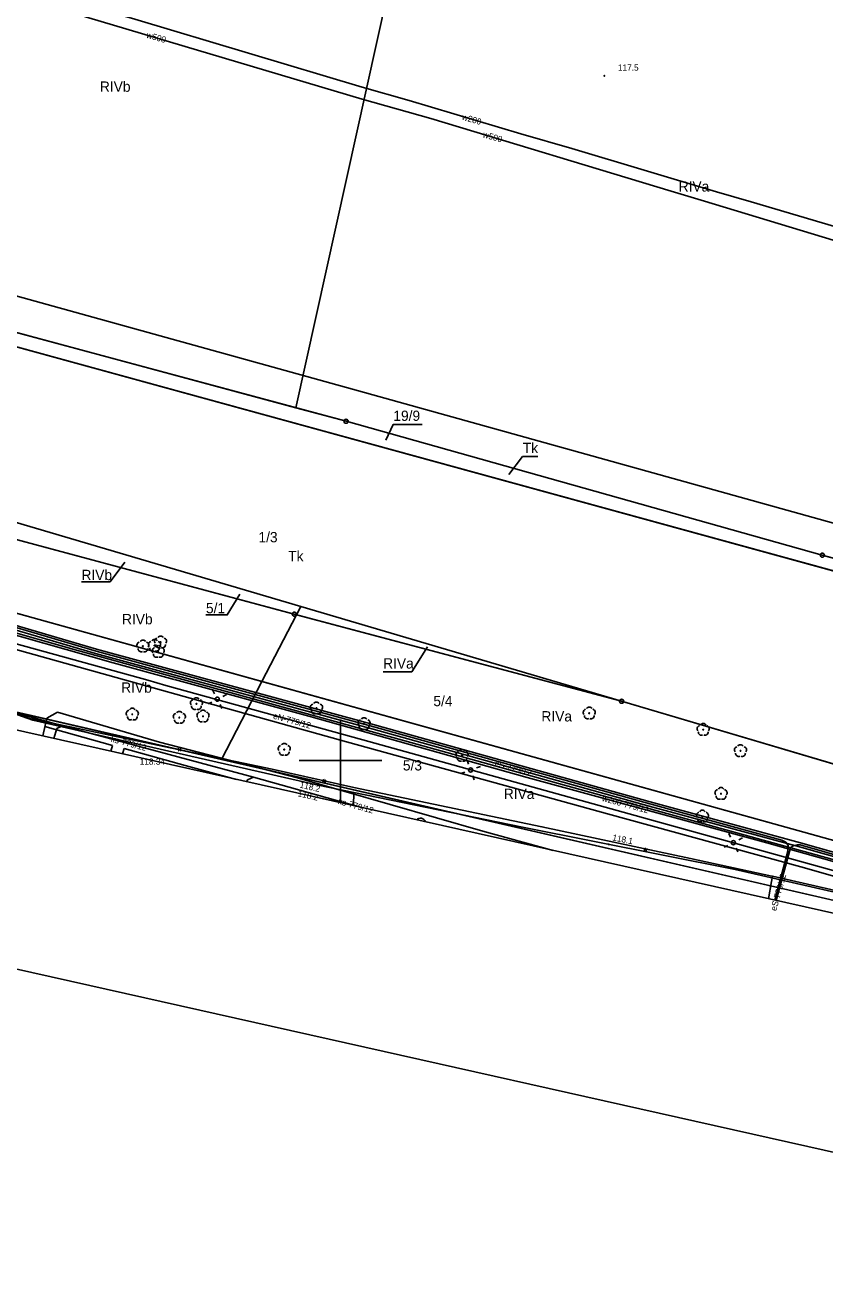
# Model space of a CAD drawing. Extents: x 6424617 to 6425697, y 5665845 to 5667190.
# Drawn here: x 6424861.7 to 6424958.8, y 5665936 to 5666089.2 of the extents above; entities that cross this region are included whole.
import ezdxf

# ---------------------------------------------------------------- set-up
doc = ezdxf.new("R2010")
doc.units = 0
for name, color, linetype in [('Warstwa 1', 7, 'Continuous'), ('Warstwa 10', 7, 'Continuous'), ('Warstwa 11', 7, 'Continuous'), ('Warstwa 12', 7, 'Continuous'), ('Warstwa 13', 7, 'Continuous'), ('Warstwa 15', 7, 'Continuous'), ('Warstwa 2', 7, 'Continuous'), ('Warstwa 6', 7, 'Continuous'), ('Warstwa 62', 7, 'Continuous'), ('Warstwa 63', 7, 'Continuous'), ('Warstwa 8', 7, 'Continuous')]:
    doc.layers.add(name, color=color, linetype=linetype)

msp = doc.modelspace()

# ---------------------------------------------------------------- linework, layer by layer
at = {"layer": 'Warstwa 1'}
for p, q in [((6424894.58, 5666042.82), (6424908.97, 5666107.79)), ((6424894.58, 5666042.82), (6424908.97, 5666107.79)), ((6424836.07, 5666058.54), (6424894.58, 5666042.82)), ((6424836.07, 5666058.54), (6424894.58, 5666042.82)), ((6424835.72, 5666057.05), (6424969.12, 5666020.47)), ((6424835.72, 5666057.05), (6424969.12, 5666020.47)), ((6424894.58, 5666042.82), (6424900.68, 5666041.18)), ((6424894.58, 5666042.82), (6424900.68, 5666041.18)), ((6424900.68, 5666041.18), (6424958.47, 5666024.93)), ((6424900.68, 5666041.18), (6424958.47, 5666024.93)), ((6424860.53, 5666028.94), (6424895.19, 5666018.7)), ((6424860.53, 5666028.94), (6424895.19, 5666018.7)), ((6424860.2, 5666026.96), (6424894.67, 5666017.7)), ((6424860.2, 5666026.96), (6424894.67, 5666017.7)), ((6424958.47, 5666024.93), (6424969.49, 5666021.95)), ((6424958.47, 5666024.93), (6424969.49, 5666021.95)), ((6424858.78, 5666018.4), (6424890.46, 5666009.6)), ((6424858.78, 5666018.4), (6424890.46, 5666009.6)), ((6424890.46, 5666009.6), (6424894.67, 5666017.7)), ((6424890.46, 5666009.6), (6424894.67, 5666017.7)), ((6424894.67, 5666017.7), (6424895.19, 5666018.7)), ((6424894.67, 5666017.7), (6424895.19, 5666018.7)), ((6424894.67, 5666017.7), (6424934.12, 5666007.2)), ((6424894.67, 5666017.7), (6424934.12, 5666007.2)), ((6424895.19, 5666018.7), (6424934.12, 5666007.2)), ((6424895.19, 5666018.7), (6424934.12, 5666007.2)), ((6424885.54, 5666000.14), (6424890.46, 5666009.6)), ((6424885.54, 5666000.14), (6424890.46, 5666009.6)), ((6424890.46, 5666009.6), (6424961.6, 5665989.83)), ((6424890.46, 5666009.6), (6424961.6, 5665989.83)), ((6424856.84, 5666006.75), (6424885.54, 5666000.14)), ((6424856.84, 5666006.75), (6424885.54, 5666000.14)), ((6424934.12, 5666007.2), (6424963.73, 5665998.45)), ((6424934.12, 5666007.2), (6424963.73, 5665998.45)), ((6424885.54, 5666000.14), (6424959.92, 5665983.01)), ((6424885.54, 5666000.14), (6424959.92, 5665983.01))]:
    msp.add_line(p, q, dxfattribs=at)
at = {"layer": 'Warstwa 10'}
for points in [[(6424857.53, 5666006.67), (6424862.3, 5666005.11), (6424867.94, 5666003.94), (6424882.04, 5666001), (6424891.71, 5665998.95), (6424901.61, 5665996.74)], [(6424952.41, 5665985.97), (6424952.35, 5665985.99), (6424942.46, 5665988.12), (6424924.44, 5665991.97), (6424901.61, 5665996.74)], [(6425060.44, 5665958.92), (6425057.61, 5665959.71), (6425030.82, 5665967.28), (6425026.23, 5665968.58), (6425020.29, 5665970.3), (6425010.94, 5665972.53), (6424974.55, 5665980.91), (6424952.41, 5665985.97)]]:
    msp.add_lwpolyline(points, dxfattribs=at)
for centre in [(6424900.68, 5666041.18), (6424958.47, 5666024.93), (6424894.39, 5666017.77), (6424934.12, 5666007.2)]:
    msp.add_circle(centre, 0.25, dxfattribs=at)
at = {"layer": 'Warstwa 11'}
for centre in [(6424878.16, 5666014.36), (6424876.02, 5666013.88), (6424877.43, 5666013.96), (6424877.88, 5666013.21), (6424882.51, 5666006.89), (6424874.73, 5666005.61), (6424880.44, 5666005.22), (6424883.31, 5666005.37), (6424897.08, 5666006.35), (6424930.19, 5666005.74), (6424902.86, 5666004.45), (6424944.02, 5666003.75), (6424893.17, 5666001.34), (6424914.75, 5666000.61), (6424948.54, 5666001.18), (6424946.18, 5665995.98), (6424943.92, 5665993.23)]:
    msp.add_circle(centre, 0.05, dxfattribs=at)
for centre, start, end in [((6424875.66, 5666014), 102.1471, 221.8529), ((6424876.02, 5666014.25), 30.1471, 149.8529), ((6424876.38, 5666014), 318.1471, 77.8529), ((6424877.07, 5666014.08), 102.1471, 221.8529), ((6424877.43, 5666014.33), 30.1471, 149.8529), ((6424877.8, 5666014.48), 102.1471, 221.8529), ((6424878.16, 5666014.74), 30.1471, 149.8529), ((6424877.79, 5666014.08), 318.1471, 77.8529), ((6424878.52, 5666014.48), 318.1471, 77.8529), ((6424875.8, 5666013.58), 174.1471, 293.8529), ((6424876.24, 5666013.58), 246.1471, 5.8529), ((6424877.21, 5666013.66), 174.1471, 293.8529), ((6424877.52, 5666013.33), 102.1471, 221.8529), ((6424877.66, 5666012.91), 174.1471, 293.8529), ((6424877.65, 5666013.66), 246.1471, 5.8529), ((6424877.94, 5666014.06), 174.1471, 293.8529), ((6424877.88, 5666013.58), 30.1471, 149.8529), ((6424878.1, 5666012.91), 246.1471, 5.8529), ((6424878.38, 5666014.06), 246.1471, 5.8529), ((6424878.24, 5666013.33), 318.1471, 77.8529), ((6424882.15, 5666007.01), 102.1471, 221.8529), ((6424882.29, 5666006.59), 174.1471, 293.8529), ((6424882.51, 5666007.26), 30.1471, 149.8529), ((6424882.73, 5666006.59), 246.1471, 5.8529), ((6424882.87, 5666007.01), 318.1471, 77.8529), ((6424896.72, 5666006.47), 102.1471, 221.8529), ((6424897.08, 5666006.73), 30.1471, 149.8529), ((6424897.44, 5666006.47), 318.1471, 77.8529), ((6424874.37, 5666005.73), 102.1471, 221.8529), ((6424874.51, 5666005.31), 174.1471, 293.8529), ((6424874.73, 5666005.99), 30.1471, 149.8529), ((6424874.95, 5666005.31), 246.1471, 5.8529), ((6424875.09, 5666005.73), 318.1471, 77.8529), ((6424880.08, 5666005.34), 102.1471, 221.8529), ((6424880.44, 5666005.59), 30.1471, 149.8529), ((6424880.8, 5666005.34), 318.1471, 77.8529), ((6424882.95, 5666005.49), 102.1471, 221.8529), ((6424883.09, 5666005.07), 174.1471, 293.8529), ((6424883.31, 5666005.75), 30.1471, 149.8529), ((6424883.53, 5666005.07), 246.1471, 5.8529), ((6424883.67, 5666005.49), 318.1471, 77.8529), ((6424896.86, 5666006.05), 174.1471, 293.8529), ((6424897.3, 5666006.05), 246.1471, 5.8529), ((6424902.86, 5666004.83), 30.1471, 149.8529), ((6424929.83, 5666005.86), 102.1471, 221.8529), ((6424929.97, 5666005.44), 174.1471, 293.8529), ((6424930.19, 5666006.12), 30.1471, 149.8529), ((6424930.41, 5666005.44), 246.1471, 5.8529), ((6424930.55, 5666005.86), 318.1471, 77.8529), ((6424880.22, 5666004.92), 174.1471, 293.8529), ((6424880.66, 5666004.92), 246.1471, 5.8529), ((6424902.5, 5666004.57), 102.1471, 221.8529), ((6424902.64, 5666004.15), 174.1471, 293.8529), ((6424903.08, 5666004.15), 246.1471, 5.8529), ((6424903.22, 5666004.57), 318.1471, 77.8529), ((6424943.66, 5666003.87), 102.1471, 221.8529), ((6424944.02, 5666004.12), 30.1471, 149.8529), ((6424944.38, 5666003.87), 318.1471, 77.8529), ((6424893.17, 5666001.71), 30.1471, 149.8529), ((6424943.8, 5666003.45), 174.1471, 293.8529), ((6424944.24, 5666003.45), 246.1471, 5.8529), ((6424892.81, 5666001.46), 102.1471, 221.8529), ((6424892.95, 5666001.04), 174.1471, 293.8529), ((6424893.39, 5666001.04), 246.1471, 5.8529), ((6424893.53, 5666001.46), 318.1471, 77.8529), ((6424914.39, 5666000.73), 102.1471, 221.8529), ((6424914.75, 5666000.99), 30.1471, 149.8529), ((6424915.11, 5666000.73), 318.1471, 77.8529), ((6424948.18, 5666001.3), 102.1471, 221.8529), ((6424948.32, 5666000.88), 174.1471, 293.8529), ((6424948.54, 5666001.55), 30.1471, 149.8529), ((6424948.76, 5666000.88), 246.1471, 5.8529), ((6424948.9, 5666001.3), 318.1471, 77.8529), ((6424914.53, 5666000.31), 174.1471, 293.8529), ((6424914.97, 5666000.31), 246.1471, 5.8529), ((6424945.82, 5665996.1), 102.1471, 221.8529), ((6424946.18, 5665996.36), 30.1471, 149.8529), ((6424946.54, 5665996.1), 318.1471, 77.8529), ((6424945.96, 5665995.68), 174.1471, 293.8529), ((6424946.4, 5665995.68), 246.1471, 5.8529), ((6424943.56, 5665993.35), 102.1471, 221.8529), ((6424943.7, 5665992.93), 174.1471, 293.8529), ((6424943.92, 5665993.61), 30.1471, 149.8529), ((6424944.14, 5665992.93), 246.1471, 5.8529), ((6424944.28, 5665993.35), 318.1471, 77.8529)]:
    msp.add_arc(centre, 0.375, start, end, dxfattribs=at)
at = {"layer": 'Warstwa 12'}
for points in [[(6424670.55, 5666139.91), (6424698.76, 5666131.82), (6424719.05, 5666126.08), (6424734.31, 5666121.24), (6424747.33, 5666117.09), (6424755.84, 5666114.39), (6424782.04, 5666115.46), (6424794.27, 5666116), (6424797.46, 5666115.3), (6424803.11, 5666113.21), (6424814.01, 5666109.23), (6424817.9, 5666107.86), (6424829.59, 5666103.93), (6424845.05, 5666099.1), (6424865.08, 5666092.88), (6424875.03, 5666089.96), (6424902.64, 5666081.73)], [(6424902.62, 5666080.27), (6424864.14, 5666091.7), (6424860.63, 5666092.76), (6424847.91, 5666096.78), (6424844.38, 5666097.93), (6424839.02, 5666099.64), (6424837.77, 5666100.03), (6424836.46, 5666100.46), (6424831.87, 5666102), (6424826.41, 5666103.77), (6424815.64, 5666107.27), (6424797.06, 5666114.5), (6424794.67, 5666114.9), (6424793, 5666114.76), (6424775.51, 5666113.22), (6424757.94, 5666111.72), (6424745.4, 5666115.53), (6424721.25, 5666122.92), (6424708.57, 5666126.76), (6424700.98, 5666128.93), (6424670.1, 5666137.9)], [(6424902.64, 5666081.73), (6424908.32, 5666080.09), (6424921.88, 5666076.04), (6424928.08, 5666074.29), (6424945.63, 5666069.01)], [(6424902.62, 5666080.27), (6424910.96, 5666077.91), (6424940.11, 5666069.08)], [(6424809.94, 5666070.66), (6424827.91, 5666065.56), (6424854, 5666058.2), (6424902.19, 5666044.87)], [(6424940.11, 5666069.08), (6424943.78, 5666067.99), (6424962.88, 5666062.22), (6424972.24, 5666059.43), (6424989.04, 5666054.69), (6425022.79, 5666045.28), (6425030.07, 5666043.18), (6425037.86, 5666041), (6425041.81, 5666039.94), (6425072.97, 5666031.24), (6425127.39, 5666016.19)], [(6425192.87, 5665999.59), (6425180.06, 5666003.17), (6425173.22, 5666005.07), (6425118.59, 5666020.43), (6425101.46, 5666025.04), (6425073.28, 5666032.33), (6425066.83, 5666034.26), (6425056.27, 5666037.28), (6425042.06, 5666041.29), (6425038.43, 5666042.25), (6425029.69, 5666044.78), (6425018.65, 5666047.88), (6425012.55, 5666049.67), (6425008.91, 5666050.68), (6424997.2, 5666054.03), (6424972.82, 5666060.99), (6424949.85, 5666067.81), (6424945.63, 5666069.01)], [(6424902.19, 5666044.87), (6425001.23, 5666017.3), (6425013.02, 5666014.09), (6425115, 5665985.63), (6425128.06, 5665981.98), (6425136.27, 5665979.57), (6425176.94, 5665968.42), (6425209.55, 5665959.16), (6425214.47, 5665958.42), (6425209.55, 5665959.16)], [(6424952.41, 5665985.97), (6424952.29, 5665985.34), (6424951.96, 5665983.24)]]:
    msp.add_lwpolyline(points, dxfattribs=at)
at = {"layer": 'Warstwa 13'}
for centre in [(6424932.01, 5666083.1), (6424897.27, 5665997.03), (6424932.55, 5665989.83)]:
    msp.add_circle(centre, 0.045, dxfattribs=at)
at = {"layer": 'Warstwa 15'}
for points in [[(6424909.92, 5666040.79), (6424906.4, 5666040.79), (6424905.52, 5666038.89)], [(6424883.67, 5666017.68), (6424886.25, 5666017.68), (6424887.78, 5666020.19)]]:
    msp.add_lwpolyline(points, dxfattribs=at)
at = {"layer": 'Warstwa 2'}
for points in [[(6424923.96, 5666036.9), (6424922.1, 5666036.9), (6424920.44, 5666034.7)], [(6424868.56, 5666021.69), (6424872.03, 5666021.69), (6424873.81, 5666024.06)], [(6424905.16, 5666010.77), (6424908.65, 5666010.77), (6424910.55, 5666013.82)]]:
    msp.add_lwpolyline(points, dxfattribs=at)
at = {"layer": 'Warstwa 6'}
for points in [[(6424995.09, 5666125.71), (6424929.13, 5666143.29), (6424860.07, 5666161.72), (6424858.37, 5666154.63), (6424848.43, 5666111.78), (6424836.07, 5666058.54), (6424900.68, 5666041.18), (6424958.47, 5666024.93), (6424969.49, 5666021.95)], [(6424900.68, 5666041.18), (6424836.07, 5666058.54), (6424835.72, 5666057.05), (6424969.12, 5666020.47), (6424969.49, 5666021.95), (6424958.47, 5666024.93)], [(6424860.53, 5666028.94), (6424934.12, 5666007.2), (6424894.39, 5666017.77), (6424860.2, 5666026.96)], [(6424860.2, 5666026.96), (6424894.39, 5666017.77), (6424934.12, 5666007.2), (6424963.73, 5665998.45), (6424961.6, 5665989.83), (6424858.78, 5666018.4)], [(6424858.78, 5666018.4), (6424961.6, 5665989.83), (6424959.92, 5665983.01), (6424856.84, 5666006.75)]]:
    msp.add_lwpolyline(points, close=True, dxfattribs=at)
for points in [[(6425247.92, 5665916.88), (6425244.9, 5665943.26), (6425213.05, 5665952.08), (6425191.26, 5665958.12), (6425175.28, 5665962.55), (6425160.35, 5665966.67), (6425114.34, 5665979.37), (6425066.83, 5665992.22), (6424969.12, 5666020.47), (6424835.72, 5666057.05), (6424831.92, 5666058.14), (6424794.14, 5666069.49), (6424779.33, 5666074.24), (6424752.27, 5666082.9), (6424722.03, 5666092.61), (6424673.98, 5666108.22), (6424664.2, 5666111.59)], [(6424658.97, 5666088.29), (6424687.91, 5666078.9), (6424716.67, 5666070.32), (6424715.7, 5666065.72), (6424712.33, 5666049.73), (6424785.75, 5666034.72), (6424788.43, 5666045.53), (6424790.34, 5666053.24), (6424828.33, 5666041.07), (6424860.53, 5666028.94), (6424934.12, 5666007.2), (6424963.73, 5665998.45), (6425016.62, 5665983.17), (6425073.51, 5665966.43), (6425123.83, 5665952.42), (6425122.41, 5665946.75), (6425151.64, 5665938.47)], [(6425042.51, 5665962.94), (6424959.92, 5665983.01), (6424856.84, 5666006.75), (6424825.41, 5666018.09), (6424784.69, 5666030.41), (6424784.21, 5666028.45), (6424710.62, 5666041.57), (6424651.3, 5666054.07)]]:
    msp.add_lwpolyline(points, dxfattribs=at)
at = {"layer": 'Warstwa 62'}
for p, q in [((6424852.22, 5666017.86), (6424867.96, 5666013.39)), ((6424855.81, 5666017.55), (6424870.34, 5666013.29)), ((6424855.87, 5666017.77), (6424870.4, 5666013.51)), ((6424853.22, 5666016.19), (6424876.6, 5666009.76)), ((6424855.28, 5666016.7), (6424872.42, 5666011.88)), ((6424855.73, 5666017.26), (6424870.26, 5666013.01)), ((6424853.91, 5666015.36), (6424899.99, 5666002.49)), ((6424867.96, 5666013.39), (6424899.34, 5666004.74)), ((6424870.26, 5666013.01), (6424903.98, 5666003.82)), ((6424870.34, 5666013.29), (6424904.06, 5666004.11)), ((6424870.4, 5666013.51), (6424904.12, 5666004.33)), ((6424872.42, 5666011.88), (6424879.8, 5666009.86)), ((6424842.41, 5666010.88), (6424866.24, 5666004.23)), ((6424876.6, 5666009.76), (6424878.8, 5666009.13)), ((6424879.84, 5666009.85), (6424896.14, 5666005.39)), ((6424878.8, 5666009.13), (6424902.71, 5666002.51)), ((6424863.89, 5666002.99), (6424864.34, 5666005.13)), ((6424864.34, 5666005.13), (6424865.65, 5666005.87)), ((6424865.65, 5666005.87), (6424878.02, 5666002.22)), ((6424896.14, 5666005.39), (6424922.66, 5665997.95)), ((6424864.13, 5666004.15), (6424872.33, 5666001.83)), ((6424865.22, 5666002.69), (6424865.56, 5666003.89)), ((6424865.56, 5666003.89), (6424866.24, 5666004.23)), ((6424866.24, 5666004.23), (6424889.44, 5665997.99)), ((6424899.34, 5666004.74), (6424926.46, 5665997.22)), ((6424903.98, 5666003.82), (6424937.46, 5665994.48)), ((6424904.06, 5666004.11), (6424937.54, 5665994.77)), ((6424904.12, 5666004.33), (6424937.6, 5665994.99)), ((6424878.02, 5666002.22), (6424894.79, 5665997.9)), ((6424899.99, 5666002.49), (6424932.4, 5665993.52)), ((6424902.71, 5666002.51), (6424947.68, 5665990.04)), ((6424872.13, 5666001.14), (6424872.33, 5666001.83)), ((6424873.56, 5666000.82), (6424873.73, 5666001.48)), ((6424873.73, 5666001.48), (6424881.14, 5665999.42)), ((6424881.14, 5665999.42), (6424887.39, 5665997.72)), ((6424888.65, 5665997.43), (6424888.71, 5665997.65)), ((6424888.71, 5665997.65), (6424889.44, 5665997.99)), ((6424889.44, 5665997.99), (6424902.71, 5665994.28)), ((6424894.79, 5665997.9), (6424917.27, 5665991.44)), ((6424922.66, 5665997.95), (6424951.76, 5665990.04)), ((6424926.46, 5665997.22), (6424969.92, 5665985.17)), ((6424937.46, 5665994.48), (6424955.7, 5665989.53)), ((6424937.54, 5665994.77), (6424953.57, 5665990.36)), ((6424937.6, 5665994.99), (6424955.84, 5665990.03)), ((6424932.4, 5665993.52), (6424955.87, 5665987.1)), ((6424917.27, 5665991.44), (6424925.82, 5665989.1)), ((6424947.68, 5665990.04), (6424963.78, 5665985.56)), ((6424951.76, 5665990.04), (6424985.73, 5665980.44)), ((6424953.57, 5665990.36), (6424954.05, 5665990.11)), ((6424954.05, 5665990.11), (6424954.33, 5665989.69)), ((6424954.92, 5665989.64), (6424955.43, 5665989.78)), ((6424955.43, 5665989.78), (6424955.77, 5665989.77)), ((6424955.77, 5665989.77), (6424979.42, 5665983.04)), ((6424955.84, 5665990.03), (6424979.49, 5665983.29)), ((6424952.71, 5665983.07), (6424954.3, 5665989.02)), ((6424952.86, 5665983.04), (6424954.62, 5665989.42)), ((6424954.3, 5665989.02), (6424954.33, 5665989.69)), ((6424954.62, 5665989.42), (6424954.92, 5665989.64)), ((6424955.7, 5665989.53), (6424979.35, 5665982.79)), ((6424955.87, 5665987.1), (6424982.88, 5665979.41))]:
    msp.add_line(p, q, dxfattribs=at)
for points in [[(6424884.7, 5666008.12), (6424884.47, 5666008.57)], [(6424884.37, 5666007.11), (6424883.92, 5666006.89)], [(6424885.38, 5666006.79), (6424885.6, 5666006.34)], [(6424885.7, 5666007.79), (6424886.15, 5666008.02)], [(6424880.31, 5666001.14), (6424880.66, 5666001.5)], [(6424880.31, 5666001.5), (6424880.66, 5666001.14)], [(6424915.54, 5665999.57), (6424915.38, 5666000.04)], [(6424916.5, 5665999.11), (6424916.97, 5665999.28)], [(6424897.8, 5665997.43), (6424898.25, 5665997.64)], [(6424897.92, 5665997.76), (6424898.13, 5665997.31)], [(6424915.09, 5665998.61), (6424914.62, 5665998.44)], [(6424916.05, 5665998.15), (6424916.21, 5665997.68)], [(6424947.34, 5665990.71), (6424947.12, 5665991.16)], [(6424948.35, 5665990.38), (6424948.79, 5665990.61)], [(6424936.8, 5665989.1), (6424937.25, 5665989.31)], [(6424936.92, 5665989.43), (6424937.13, 5665988.98)], [(6424947.01, 5665989.71), (6424946.56, 5665989.48)], [(6424948.01, 5665989.37), (6424948.24, 5665988.93)]]:
    msp.add_lwpolyline(points, dxfattribs=at)
for centre in [(6424885.04, 5666007.45), (6424915.79, 5665998.86), (6424947.68, 5665990.04)]:
    msp.add_circle(centre, 0.25, dxfattribs=at)
msp.add_arc((6424909.68, 5665992.33), 0.682, 20.73, 133.9958, dxfattribs=at)
at = {"layer": 'Warstwa 63'}
for p, q in [((6424900, 5666005), (6424900, 5665995)), ((6424905, 5666000), (6424895, 5666000))]:
    msp.add_line(p, q, dxfattribs=at)
for points in [[(6424616.75, 5666029.38), (6424876.88, 5667189.58), (6425697.3, 5667005.64), (6425437.18, 5665845.44)], [(6425341.16, 5665895.98), (6425588.9, 5667000.93), (6424898.31, 5667155.76), (6424650.57, 5666050.81)]]:
    msp.add_lwpolyline(points, close=True, dxfattribs=at)
at = {"layer": 'Warstwa 8'}
for p, q in [((6424848.24, 5666009.92), (6424862.65, 5666004.92)), ((6424862.65, 5666004.92), (6424897.27, 5665997.03)), ((6424897.27, 5665997.03), (6424901.6, 5665996.14)), ((6424901.58, 5665994.54), (6424901.6, 5665996.14)), ((6424901.58, 5665994.54), (6424901.6, 5665996.14)), ((6424901.6, 5665996.14), (6424922.08, 5665991.92)), ((6424922.08, 5665991.92), (6424947.91, 5665986.77)), ((6424947.91, 5665986.77), (6424972.57, 5665981.16))]:
    msp.add_line(p, q, dxfattribs=at)
msp.add_lwpolyline([(6424952.3, 5665985.38), (6424952.29, 5665985.34), (6424951.96, 5665983.24)], dxfattribs=at)

# ---------------------------------------------------------------- texts
at = {"layer": 'Warstwa 13'}
for s, rotation, p in [('w500', 344.0898, (6424876.38, 5666087.73)), ('w200', 344.0726, (6424914.67, 5666077.78)), ('w500', 344.2388, (6424917.21, 5666075.65)), ('118.2', 347.1666, (6424894.99, 5665996.73)), ('118.2', 347.1666, (6424894.76, 5665995.68)), ('118.1', 348.725, (6424932.95, 5665990.33))]:
    msp.add_text(s, height=0.75, rotation=rotation, dxfattribs=at).set_placement(p)
msp.add_text('117.5', height=0.75, dxfattribs=at).set_placement((6424933.67, 5666083.72))
at = {"layer": 'Warstwa 15'}
for s, height, p in [('19/9', 1.25, (6424906.41, 5666041.22)), ('1/3', 1.25, (6424890.04, 5666026.49)), ('5/1', 1.25, (6424883.67, 5666017.88)), ('5/4', 1.25, (6424911.27, 5666006.6)), ('118.34', 0.75, (6424875.63, 5665999.5)), ('5/3', 1.25, (6424907.57, 5665998.8))]:
    msp.add_text(s, height=height, dxfattribs=at).set_placement(p)
at = {"layer": 'Warstwa 2'}
for s, p in [('RIVb', (6424870.8, 5666081.16)), ('RIVa', (6424941.04, 5666069.05)), ('Tk', (6424922.12, 5666037.32)), ('Tk', (6424893.65, 5666024.19)), ('RIVb', (6424868.56, 5666021.9)), ('RIVb', (6424873.48, 5666016.54)), ('RIVa', (6424905.17, 5666011.17)), ('RIVb', (6424873.38, 5666008.24)), ('RIVa', (6424924.38, 5666004.75)), ('RIVa', (6424919.82, 5665995.34))]:
    msp.add_text(s, height=1.25, dxfattribs=at).set_placement(p)
at = {"layer": 'Warstwa 62'}
for s, rotation, p in [('eN-779/12', 344.7449, (6424891.76, 5666005.1)), ('ks-779/12', 344.9488, (6424872.08, 5666002.3)), ('eS-779/12', 344.4118, (6424918.63, 5665999.35)), ('ks-779/12', 344.3931, (6424899.64, 5665994.75)), ('w200-779/12', 344.8039, (6424931.69, 5665995.11)), ('eS-779/12', 74.5749, (6424952.88, 5665981.7))]:
    msp.add_text(s, height=0.75, rotation=rotation, dxfattribs=at).set_placement(p)

doc.saveas('drawing.dxf')
